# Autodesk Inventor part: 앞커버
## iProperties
Company: 한국ATC센터
Created: 2014-08
Part Number: 앞커버
Document SubType Name: Modeling
Designer: KYOUNG IL JANG
Density: 2.71 g/cm^3
Material: 알루미늄-6061
Mass: 241.248 g
Surface Area: 231.959 cm^2
Volume: 89.0213 cm^3
Author: KYOUNG IL JANG
